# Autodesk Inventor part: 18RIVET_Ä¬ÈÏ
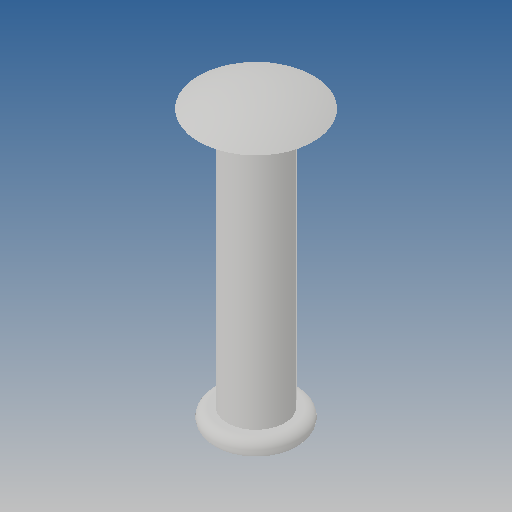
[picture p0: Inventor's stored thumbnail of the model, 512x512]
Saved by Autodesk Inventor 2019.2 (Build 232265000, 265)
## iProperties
Created: 2010-06
Part Number: 18RIVET_Ä¬ÈÏ
Material: Ogólny
Document SubType Name: Modeling
Designer: CADENGINEERING4
Density: 1 g/cm^3
Appearance: Domyślna
Author: CADENGINEERING4
Revision Number: ÈÎºÎ
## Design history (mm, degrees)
feature "NONE"
node "Bryła1"
